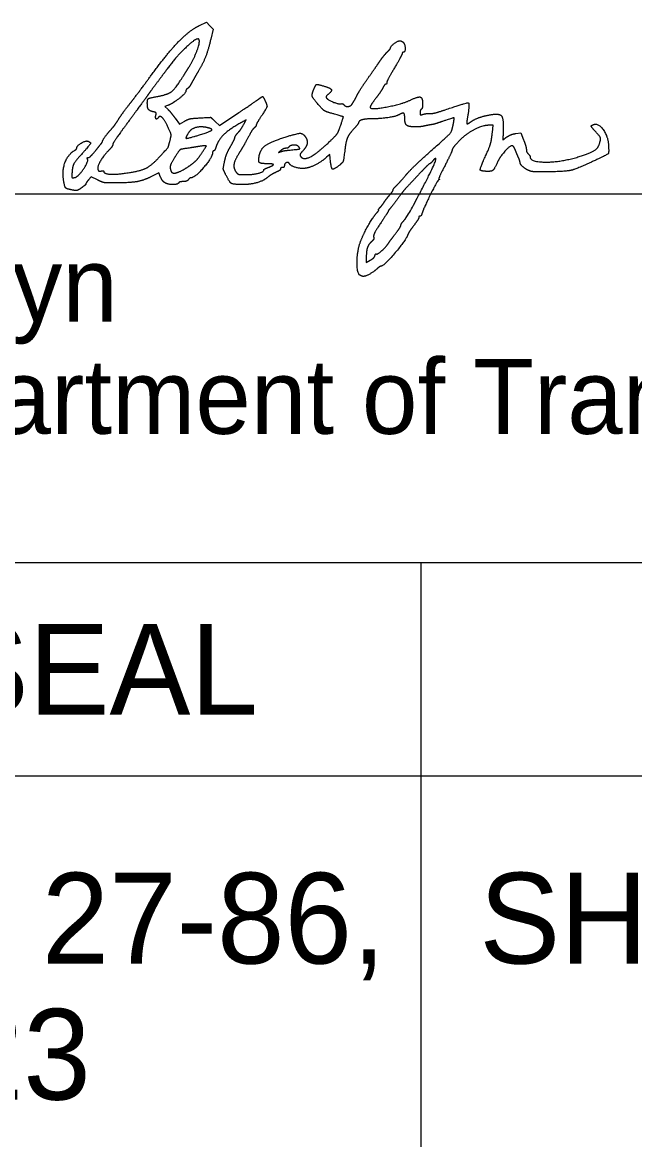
# Model space of a CAD drawing. Extents: x -21.9 to 47.3, y 14.1 to 48.7.
# Drawn here: x 25.653 to 26.801, y 33.152 to 35.245 of the extents above; entities that cross this region are included whole.
import ezdxf

# ---------------------------------------------------------------- set-up
doc = ezdxf.new("R2010")
doc.units = 0
for name, color, linetype in [('GM_X_City_Street', 7, 'Continuous'), ('SH_Data', 7, 'Continuous'), ('SH_Text', 7, 'Continuous')]:
    doc.layers.add(name, color=color, linetype=linetype)

msp = doc.modelspace()

# ---------------------------------------------------------------- linework, layer by layer
at = {"layer": 'GM_X_City_Street'}
for points in [[(25.9853, 35.2396), (25.9979, 35.2455), (26.0042, 35.2391), (26.0106, 35.2327), (26.0062, 35.214)], [(25.9253, 35.0896), (25.9203, 35.088), (25.9255, 35.0829)], [(26.0143, 35.0599), (26.0224, 35.0523), (26.0587, 35.0764)], [(25.9392, 35.0662), (25.9477, 35.0547), (25.9565, 35.0599)], [(26.0682, 35.0547), (26.0726, 35.0626), (26.0671, 35.0597)], [(26.534, 35.0388), (26.5355, 35.0526), (26.5277, 35.0526)], [(26.5779, 35.0371), (26.5876, 35.0387), (26.5926, 35.0251)], [(26.23, 34.991), (26.2293, 34.9978), (26.2234, 34.9927)], [(25.9123, 34.9554), (25.909, 34.9634), (25.8951, 34.9565)], [(25.7937, 34.9503), (25.7822, 34.9561), (25.7771, 34.9503)], [(26.2977, 34.8049), (26.2977, 34.7955), (26.3052, 34.7998)]]:
    msp.add_lwpolyline(points, dxfattribs=at)
for points in [[(25.8957, 35.1477), (25.9254, 35.1883), (25.9672, 35.2312), (25.9853, 35.2396)], [(25.9838, 35.2138), (25.9802, 35.2174), (25.9416, 35.1817), (25.9262, 35.1604)], [(25.9655, 35.1618), (25.9749, 35.1766), (25.9869, 35.2107), (25.9838, 35.2138)], [(26.0062, 35.214), (26.0012, 35.1929), (25.992, 35.1693), (25.9826, 35.1534)], [(26.3367, 35.1896), (26.3403, 35.1932), (26.3433, 35.1969), (26.3433, 35.1977)], [(26.3433, 35.1977), (26.3433, 35.2005), (26.3565, 35.2108), (26.3602, 35.2109)], [(26.3602, 35.2109), (26.3623, 35.2109), (26.3652, 35.2097), (26.3668, 35.2081)], [(26.3668, 35.2081), (26.3703, 35.2046), (26.3707, 35.1894), (26.3673, 35.1894)], [(26.3013, 35.1414), (26.3092, 35.1526), (26.319, 35.1665), (26.3229, 35.1724)], [(26.3229, 35.1724), (26.3269, 35.1782), (26.3331, 35.1859), (26.3367, 35.1896)], [(26.3649, 35.1868), (26.3649, 35.1855), (26.3584, 35.1734), (26.3505, 35.16)], [(26.3673, 35.1894), (26.366, 35.1894), (26.3649, 35.1882), (26.3649, 35.1868)], [(25.9262, 35.1604), (25.9226, 35.1555), (25.9132, 35.1428), (25.9053, 35.1323)], [(25.955, 35.1451), (25.9583, 35.1503), (25.963, 35.1578), (25.9655, 35.1618)], [(25.9826, 35.1534), (25.9791, 35.1474), (25.9739, 35.1382), (25.971, 35.133)], [(26.3505, 35.16), (26.3426, 35.1466), (26.3361, 35.1342), (26.3361, 35.1325)], [(25.8555, 35.0943), (25.8644, 35.1056), (25.8825, 35.1297), (25.8957, 35.1477)], [(25.9053, 35.1323), (25.8974, 35.1218), (25.8893, 35.1108), (25.8873, 35.1079)], [(25.9052, 35.1064), (25.9258, 35.1102), (25.9398, 35.1211), (25.955, 35.1451)], [(25.971, 35.133), (25.9682, 35.1277), (25.9644, 35.1225), (25.9626, 35.1214)], [(26.2799, 35.1078), (26.2837, 35.115), (26.2933, 35.1301), (26.3013, 35.1414)], [(26.3361, 35.1325), (26.3361, 35.1308), (26.3352, 35.1294), (26.3341, 35.1294)], [(25.9593, 35.116), (25.9593, 35.1123), (25.9335, 35.0922), (25.9253, 35.0896)], [(25.9626, 35.1214), (25.9608, 35.1204), (25.9593, 35.1179), (25.9593, 35.116)], [(26.209, 35.0902), (26.1975, 35.1032), (26.1953, 35.11), (26.1992, 35.1196)], [(26.1992, 35.1196), (26.203, 35.1287), (26.2061, 35.1297), (26.2188, 35.1259)], [(26.2188, 35.1259), (26.2308, 35.1224), (26.2337, 35.1162), (26.226, 35.1104)], [(26.226, 35.1104), (26.2233, 35.1083), (26.2218, 35.1054), (26.2228, 35.1041)], [(26.3288, 35.1228), (26.3271, 35.1191), (26.3209, 35.11), (26.3152, 35.1026)], [(26.3341, 35.1294), (26.333, 35.1294), (26.3306, 35.1264), (26.3288, 35.1228)], [(25.834, 35.0649), (25.837, 35.0697), (25.8467, 35.0829), (25.8555, 35.0943)], [(25.8873, 35.1079), (25.8853, 35.1049), (25.87, 35.084), (25.8532, 35.0613)], [(25.8873, 35.0943), (25.8873, 35.1012), (25.8914, 35.1039), (25.9052, 35.1064)], [(25.8983, 35.0779), (25.8911, 35.0797), (25.8873, 35.0854), (25.8873, 35.0943)], [(26.0587, 35.0764), (26.0786, 35.0897), (26.0962, 35.1016), (26.0978, 35.1029)], [(26.0978, 35.1029), (26.1023, 35.1067), (26.1047, 35.1058), (26.1077, 35.0992)], [(26.1077, 35.0992), (26.1121, 35.0896), (26.1111, 35.0855), (26.1009, 35.0696)], [(26.2325, 35.075), (26.2217, 35.0781), (26.2168, 35.0813), (26.209, 35.0902)], [(26.2228, 35.1041), (26.2254, 35.1003), (26.2453, 35.0921), (26.25, 35.0929)], [(26.25, 35.0929), (26.2522, 35.0933), (26.2548, 35.0924), (26.2556, 35.0911)], [(26.2556, 35.0911), (26.2578, 35.0876), (26.2678, 35.0879), (26.2706, 35.0916)], [(26.2706, 35.0916), (26.2719, 35.0932), (26.2761, 35.1005), (26.2799, 35.1078)], [(26.3152, 35.1026), (26.3096, 35.0951), (26.3049, 35.0878), (26.3049, 35.0865)], [(26.3049, 35.0865), (26.3049, 35.0812), (26.3645, 35.0921), (26.3825, 35.1007)], [(26.3825, 35.1007), (26.3955, 35.1069), (26.4033, 35.1037), (26.4033, 35.0924)], [(26.4033, 35.0924), (26.4033, 35.0878), (26.4022, 35.0834), (26.4009, 35.0826)], [(26.4456, 35.0816), (26.486, 35.0955), (26.4919, 35.0939), (26.4878, 35.07)], [(25.9034, 35.0716), (25.9043, 35.0752), (25.9031, 35.0767), (25.8983, 35.0779)], [(25.9077, 35.0669), (25.9052, 35.063), (25.902, 35.0665), (25.9034, 35.0716)], [(25.9265, 35.0483), (25.9203, 35.0619), (25.9106, 35.0716), (25.9077, 35.0669)], [(25.9255, 35.0829), (25.9283, 35.0801), (25.9345, 35.0726), (25.9392, 35.0662)], [(26.1009, 35.0696), (26.0956, 35.0615), (26.0913, 35.0539), (26.0913, 35.0528)], [(26.2493, 35.0513), (26.255, 35.0681), (26.2546, 35.0687), (26.2325, 35.075)], [(26.3583, 35.0719), (26.3527, 35.0689), (26.3225, 35.0646), (26.3075, 35.0646)], [(26.3697, 35.0672), (26.3697, 35.0745), (26.366, 35.0761), (26.3583, 35.0719)], [(26.4009, 35.0826), (26.3996, 35.0817), (26.3985, 35.0789), (26.3985, 35.0762)], [(26.3985, 35.0762), (26.3985, 35.0723), (26.3995, 35.0718), (26.4039, 35.0731)], [(26.4039, 35.0731), (26.4069, 35.0741), (26.4127, 35.0747), (26.4168, 35.0746)], [(26.4168, 35.0746), (26.421, 35.0744), (26.4339, 35.0776), (26.4456, 35.0816)], [(26.4878, 35.07), (26.4865, 35.0624), (26.4857, 35.0558), (26.4862, 35.0553)], [(26.4938, 35.0592), (26.501, 35.0642), (26.5192, 35.0705), (26.5329, 35.0727)], [(26.5329, 35.0727), (26.5476, 35.075), (26.5552, 35.0646), (26.5544, 35.0433)], [(25.8177, 35.043), (25.8243, 35.0503), (25.8285, 35.0561), (25.834, 35.0649)], [(25.8532, 35.0613), (25.8364, 35.0387), (25.8226, 35.0185), (25.8225, 35.0166)], [(25.9298, 35.0238), (25.9323, 35.0336), (25.932, 35.0358), (25.9265, 35.0483)], [(25.9565, 35.0599), (25.963, 35.0638), (25.9706, 35.0655), (25.9857, 35.0664)], [(25.9975, 35.0486), (25.9866, 35.0508), (25.9693, 35.0457), (25.9649, 35.0391)], [(25.9857, 35.0664), (26.006, 35.0675), (26.0062, 35.0675), (26.0143, 35.0599)], [(25.9869, 35.0351), (26.0061, 35.041), (26.0101, 35.0461), (25.9975, 35.0486)], [(26.0671, 35.0597), (26.0437, 35.0471), (26.021, 35.0265), (26.0168, 35.014)], [(26.0554, 35.0365), (26.0608, 35.0425), (26.0633, 35.0461), (26.0682, 35.0547)], [(26.0877, 35.0478), (26.0858, 35.0462), (26.0827, 35.042), (26.0809, 35.0385)], [(26.0913, 35.0528), (26.0913, 35.0516), (26.0897, 35.0494), (26.0877, 35.0478)], [(26.231, 35.024), (26.2414, 35.034), (26.2455, 35.0402), (26.2493, 35.0513)], [(26.2833, 35.0574), (26.2833, 35.0565), (26.2791, 35.0511), (26.2739, 35.0453)], [(26.3075, 35.0646), (26.296, 35.0646), (26.2833, 35.0608), (26.2833, 35.0574)], [(26.389, 35.0496), (26.3766, 35.0496), (26.3697, 35.0559), (26.3697, 35.0672)], [(26.4057, 35.051), (26.4024, 35.0502), (26.3949, 35.0496), (26.389, 35.0496)], [(26.4189, 35.0536), (26.4149, 35.0529), (26.409, 35.0518), (26.4057, 35.051)], [(26.4161, 35.002), (26.4516, 35.0336), (26.4585, 35.0418), (26.4609, 35.055)], [(26.4403, 35.0597), (26.4325, 35.057), (26.4229, 35.0542), (26.4189, 35.0536)], [(26.4609, 35.055), (26.463, 35.0665), (26.4613, 35.0669), (26.4403, 35.0597)], [(26.5277, 35.0526), (26.515, 35.0526), (26.4812, 35.0341), (26.4691, 35.0206)], [(26.4862, 35.0553), (26.4867, 35.0548), (26.4901, 35.0566), (26.4938, 35.0592)], [(26.7245, 35.0439), (26.7192, 35.0496), (26.719, 35.0523), (26.7236, 35.054)], [(26.7236, 35.054), (26.7322, 35.0573), (26.7506, 35.0324), (26.7516, 35.0161)], [(25.8033, 35.0225), (25.8033, 35.0242), (25.8124, 35.0372), (25.8177, 35.043)], [(25.9649, 35.0391), (25.9579, 35.0284), (25.9625, 35.0276), (25.9869, 35.0351)], [(26.0429, 35.0124), (26.0473, 35.0201), (26.0512, 35.0278), (26.0514, 35.0295)], [(26.0514, 35.0295), (26.0517, 35.0312), (26.0535, 35.0344), (26.0554, 35.0365)], [(26.0809, 35.0385), (26.0727, 35.0231), (26.0649, 35.0093), (26.0588, 34.9996)], [(26.0971, 34.9957), (26.0992, 35.007), (26.1154, 35.0204), (26.1347, 35.0268)], [(26.1347, 35.0268), (26.1665, 35.0374), (26.1799, 35.0378), (26.185, 35.0284)], [(26.185, 35.0284), (26.1882, 35.0223), (26.1848, 35.0109), (26.1774, 35.003)], [(26.2739, 35.0453), (26.2655, 35.0359), (26.2597, 35.0233), (26.2581, 35.0106)], [(26.5194, 34.9909), (26.5284, 35.0108), (26.5324, 35.024), (26.534, 35.0388)], [(26.5544, 35.0433), (26.5537, 35.0249), (26.5536, 35.0252), (26.5613, 35.0307)], [(26.5613, 35.0307), (26.5651, 35.0334), (26.5726, 35.0363), (26.5779, 35.0371)], [(26.7336, 35.0148), (26.7376, 35.0266), (26.736, 35.0315), (26.7245, 35.0439)], [(25.7304, 34.9489), (25.7275, 34.9674), (25.7382, 34.9975), (25.7506, 35.0052)], [(25.7506, 35.0052), (25.7532, 35.0068), (25.7553, 35.0092), (25.7553, 35.0105)], [(25.7553, 35.0105), (25.7554, 35.0143), (25.7721, 35.0243), (25.7759, 35.0228)], [(25.7759, 35.0228), (25.7819, 35.0205), (25.7796, 35.0156), (25.7653, 34.9997)], [(25.7888, 35.0034), (25.7941, 35.01), (25.7996, 35.0167), (25.8009, 35.0182)], [(25.8151, 35.0058), (25.8053, 34.9962), (25.7929, 34.9741), (25.7947, 34.9694)], [(25.8009, 35.0182), (25.8022, 35.0198), (25.8033, 35.0218), (25.8033, 35.0225)], [(25.8225, 35.0166), (25.8224, 35.0146), (25.8191, 35.0097), (25.8151, 35.0058)], [(25.9101, 34.9933), (25.9262, 35.0108), (25.9265, 35.0113), (25.9298, 35.0238)], [(25.9677, 35.0103), (25.9499, 35.0077), (25.9479, 35.0066), (25.9406, 34.9954)], [(25.9851, 35.013), (25.9795, 35.0121), (25.9717, 35.0109), (25.9677, 35.0103)], [(25.9901, 35.0013), (25.9979, 35.0127), (25.997, 35.0148), (25.9851, 35.013)], [(26.0168, 35.014), (26.0151, 35.0088), (26.0128, 35.0046), (26.0117, 35.0046)], [(26.032, 34.9846), (26.0336, 34.9923), (26.0385, 35.0048), (26.0429, 35.0124)], [(26.138, 35.0056), (26.1334, 35.0018), (26.1334, 35.0018), (26.1381, 35.0034)], [(26.1468, 35.0094), (26.1445, 35.0094), (26.1405, 35.0076), (26.138, 35.0056)], [(26.1381, 35.0034), (26.1407, 35.0044), (26.1483, 35.0056), (26.1549, 35.0062)], [(26.1523, 35.0115), (26.1516, 35.0103), (26.1491, 35.0094), (26.1468, 35.0094)], [(26.1708, 35.0126), (26.168, 35.0159), (26.1546, 35.0151), (26.1523, 35.0115)], [(26.1549, 35.0062), (26.1716, 35.0077), (26.174, 35.0087), (26.1708, 35.0126)], [(26.174, 34.9951), (26.1793, 34.9865), (26.2061, 35), (26.231, 35.024)], [(26.2581, 35.0106), (26.2553, 34.9881), (26.2536, 34.9826), (26.2479, 34.9781)], [(26.4585, 35.006), (26.4585, 35.0044), (26.4525, 34.9916), (26.4453, 34.9774)], [(26.4691, 35.0206), (26.4632, 35.0141), (26.4585, 35.0075), (26.4585, 35.006)], [(26.5709, 35.0142), (26.5666, 35.0142), (26.5483, 34.9936), (26.5436, 34.9835)], [(26.5765, 35.0076), (26.575, 35.0112), (26.5725, 35.0142), (26.5709, 35.0142)], [(26.5824, 34.9934), (26.5806, 34.9975), (26.578, 35.0039), (26.5765, 35.0076)], [(26.5926, 35.0251), (26.5954, 35.0177), (26.5977, 35.0095), (26.5977, 35.007)], [(26.5977, 35.007), (26.5977, 35.0045), (26.5993, 35.0009), (26.6013, 34.9989)], [(26.6847, 34.9905), (26.7084, 34.9968), (26.7314, 35.0082), (26.7336, 35.0148)], [(26.7516, 35.0161), (26.7526, 35.0008), (26.7499, 34.9977), (26.7265, 34.9867)], [(25.7653, 34.9997), (25.7516, 34.9846), (25.7466, 34.9744), (25.746, 34.9606)], [(25.7509, 34.9546), (25.7572, 34.9555), (25.7773, 34.984), (25.7753, 34.9892)], [(25.7753, 34.9892), (25.7745, 34.9911), (25.7751, 34.9924), (25.7765, 34.992)], [(25.7765, 34.992), (25.7779, 34.9917), (25.7834, 34.9968), (25.7888, 35.0034)], [(25.8536, 34.9639), (25.8763, 34.9676), (25.8959, 34.9778), (25.9101, 34.9933)], [(25.9406, 34.9954), (25.9324, 34.9827), (25.9292, 34.9729), (25.9315, 34.9671)], [(25.9602, 34.9726), (25.9714, 34.9796), (25.9824, 34.9901), (25.9901, 35.0013)], [(26.0097, 35.0016), (26.0095, 34.993), (25.9764, 34.9542), (25.9693, 34.9542)], [(26.0117, 35.0046), (26.0106, 35.0046), (26.0097, 35.0032), (26.0097, 35.0016)], [(26.034, 34.9606), (26.0296, 34.9697), (26.0294, 34.9719), (26.032, 34.9846)], [(26.0588, 34.9996), (26.0508, 34.987), (26.0486, 34.9718), (26.0537, 34.965)], [(26.1106, 34.9806), (26.0991, 34.9806), (26.0951, 34.9851), (26.0971, 34.9957)], [(26.1774, 35.003), (26.1746, 35.0001), (26.1731, 34.9965), (26.174, 34.9951)], [(26.2234, 34.9927), (26.214, 34.9845), (26.194, 34.9739), (26.1849, 34.9722)], [(26.2479, 34.9781), (26.2362, 34.9689), (26.2318, 34.972), (26.23, 34.991)], [(26.3694, 34.8755), (26.3771, 34.8842), (26.4303, 34.988), (26.4282, 34.99)], [(26.372, 34.9593), (26.3792, 34.9677), (26.399, 34.9869), (26.4161, 35.002)], [(26.4225, 34.986), (26.4201, 34.983), (26.4175, 34.9806), (26.4167, 34.9806)], [(26.4282, 34.99), (26.4275, 34.9908), (26.4249, 34.9889), (26.4225, 34.986)], [(26.5267, 34.9662), (26.5122, 34.9662), (26.5106, 34.9716), (26.5194, 34.9909)], [(26.5858, 34.9838), (26.5857, 34.9849), (26.5842, 34.9892), (26.5824, 34.9934)], [(26.6013, 34.9989), (26.6033, 34.9969), (26.6049, 34.9942), (26.6049, 34.9929)], [(26.6049, 34.9929), (26.6049, 34.9844), (26.6555, 34.9829), (26.6847, 34.9905)], [(26.7265, 34.9867), (26.6917, 34.9704), (26.6707, 34.9656), (26.6313, 34.9652)], [(25.7947, 34.9694), (25.7956, 34.967), (25.7979, 34.9661), (25.8009, 34.9669)], [(25.8009, 34.9669), (25.8035, 34.9675), (25.8057, 34.9672), (25.8057, 34.9661)], [(25.8057, 34.9661), (25.8057, 34.9615), (25.8313, 34.9603), (25.8536, 34.9639)], [(25.9315, 34.9671), (25.9335, 34.9618), (25.9471, 34.9645), (25.9602, 34.9726)], [(26.0537, 34.965), (26.0566, 34.9612), (26.0601, 34.9602), (26.0713, 34.9602)], [(26.0713, 34.9602), (26.0853, 34.9601), (26.1057, 34.9653), (26.1057, 34.9688)], [(26.1057, 34.9688), (26.1057, 34.9698), (26.1094, 34.972), (26.114, 34.9736)], [(26.114, 34.9736), (26.1243, 34.9774), (26.1227, 34.9806), (26.1106, 34.9806)], [(26.1315, 34.966), (26.1242, 34.9627), (26.1165, 34.9582), (26.1123, 34.9546)], [(26.1369, 34.9709), (26.1369, 34.9695), (26.1345, 34.9673), (26.1315, 34.966)], [(26.1405, 34.9734), (26.1385, 34.9734), (26.1369, 34.9722), (26.1369, 34.9709)], [(26.1441, 34.9767), (26.1441, 34.9749), (26.1425, 34.9734), (26.1405, 34.9734)], [(26.1536, 34.9807), (26.1516, 34.984), (26.1441, 34.9808), (26.1441, 34.9767)], [(26.1849, 34.9722), (26.1763, 34.9707), (26.1565, 34.976), (26.1536, 34.9807)], [(26.4079, 34.9728), (26.4038, 34.9685), (26.3933, 34.9574), (26.3845, 34.9481)], [(26.4167, 34.9806), (26.416, 34.9806), (26.412, 34.977), (26.4079, 34.9728)], [(26.4453, 34.9774), (26.438, 34.9633), (26.4329, 34.9517), (26.4339, 34.9517)], [(26.5436, 34.9835), (26.5379, 34.9711), (26.5331, 34.9662), (26.5267, 34.9662)], [(26.6014, 34.9682), (26.5944, 34.9715), (26.5859, 34.9799), (26.5858, 34.9838)], [(26.6313, 34.9652), (26.6164, 34.965), (26.6061, 34.966), (26.6014, 34.9682)], [(25.747, 34.9312), (25.7361, 34.9332), (25.7323, 34.9373), (25.7304, 34.9489)], [(25.746, 34.9606), (25.7458, 34.955), (25.7466, 34.954), (25.7509, 34.9546)], [(25.7721, 34.9427), (25.7721, 34.9418), (25.7683, 34.9384), (25.7637, 34.9353)], [(25.7771, 34.9503), (25.7744, 34.9471), (25.7721, 34.9437), (25.7721, 34.9427)], [(25.8245, 34.9446), (25.8089, 34.9446), (25.803, 34.9457), (25.7937, 34.9503)], [(25.8951, 34.9565), (25.8796, 34.9488), (25.8544, 34.9446), (25.8245, 34.9446)], [(25.9205, 34.9447), (25.9179, 34.9462), (25.9142, 34.951), (25.9123, 34.9554)], [(25.9461, 34.9446), (25.9441, 34.9414), (25.9266, 34.9415), (25.9205, 34.9447)], [(25.9543, 34.947), (25.9506, 34.947), (25.9469, 34.9459), (25.9461, 34.9446)], [(25.9641, 34.9506), (25.9625, 34.9486), (25.9581, 34.947), (25.9543, 34.947)], [(25.9693, 34.9542), (25.9681, 34.9542), (25.9657, 34.9525), (25.9641, 34.9506)], [(26.0658, 34.9414), (26.0483, 34.9415), (26.0413, 34.9458), (26.034, 34.9606)], [(26.1123, 34.9546), (26.1046, 34.9483), (26.0803, 34.9414), (26.0658, 34.9414)], [(26.3535, 34.9389), (26.3565, 34.9417), (26.3648, 34.9509), (26.372, 34.9593)], [(26.3845, 34.9481), (26.3757, 34.9388), (26.3658, 34.9276), (26.3625, 34.9231)], [(26.4331, 34.9499), (26.4304, 34.9481), (26.4052, 34.8971), (26.4022, 34.8876)], [(26.4339, 34.9517), (26.4349, 34.9517), (26.4345, 34.9509), (26.4331, 34.9499)], [(25.7637, 34.9353), (25.7572, 34.9308), (25.7536, 34.9299), (25.747, 34.9312)], [(26.3313, 34.9085), (26.3333, 34.9116), (26.3379, 34.9176), (26.3415, 34.9218)], [(26.3625, 34.9231), (26.3544, 34.9122), (26.3439, 34.8984), (26.3409, 34.8949)], [(26.3415, 34.9218), (26.3451, 34.9261), (26.3481, 34.9305), (26.3481, 34.9317)], [(26.3481, 34.9317), (26.3482, 34.9328), (26.3506, 34.9361), (26.3535, 34.9389)], [(26.3235, 34.8986), (26.3258, 34.901), (26.3293, 34.9055), (26.3313, 34.9085)], [(26.2875, 34.8362), (26.2934, 34.851), (26.3105, 34.8809), (26.3176, 34.8888)], [(26.3176, 34.8888), (26.3203, 34.8917), (26.3218, 34.8942), (26.3209, 34.8942)], [(26.3209, 34.8942), (26.32, 34.8942), (26.3212, 34.8961), (26.3235, 34.8986)], [(26.3385, 34.891), (26.3385, 34.8904), (26.3322, 34.8805), (26.3244, 34.8688)], [(26.3409, 34.8949), (26.3396, 34.8933), (26.3385, 34.8915), (26.3385, 34.891)], [(26.3961, 34.8796), (26.3961, 34.8783), (26.3918, 34.8715), (26.3866, 34.8646)], [(26.3983, 34.8822), (26.3971, 34.8822), (26.3961, 34.881), (26.3961, 34.8796)], [(26.4022, 34.8876), (26.4013, 34.8846), (26.3996, 34.8822), (26.3983, 34.8822)], [(26.3244, 34.8688), (26.3158, 34.8558), (26.3108, 34.846), (26.3115, 34.8433)], [(26.3523, 34.8493), (26.3579, 34.8567), (26.3625, 34.8638), (26.3625, 34.8652)], [(26.3625, 34.8652), (26.3625, 34.8665), (26.3656, 34.8711), (26.3694, 34.8755)], [(26.3866, 34.8646), (26.3814, 34.8577), (26.3763, 34.8497), (26.3752, 34.8469)], [(26.3115, 34.8433), (26.3122, 34.8408), (26.3106, 34.8372), (26.3078, 34.8348)], [(26.3752, 34.8469), (26.3716, 34.837), (26.3304, 34.7886), (26.3257, 34.7886)], [(26.3397, 34.8321), (26.341, 34.8342), (26.3467, 34.842), (26.3523, 34.8493)], [(26.2857, 34.7717), (26.2798, 34.7755), (26.281, 34.8198), (26.2875, 34.8362)], [(26.3078, 34.8348), (26.3019, 34.8295), (26.2977, 34.8172), (26.2977, 34.8049)], [(26.3169, 34.8113), (26.3188, 34.8102), (26.3355, 34.8253), (26.3397, 34.8321)], [(26.3052, 34.7998), (26.3094, 34.8022), (26.3133, 34.806), (26.3139, 34.8083)], [(26.3139, 34.8083), (26.3145, 34.8106), (26.3159, 34.812), (26.3169, 34.8113)], [(26.3183, 34.784), (26.3121, 34.7783), (26.2961, 34.7693), (26.2922, 34.7694)], [(26.3257, 34.7886), (26.3243, 34.7886), (26.321, 34.7865), (26.3183, 34.784)], [(26.2922, 34.7694), (26.2906, 34.7694), (26.2877, 34.7705), (26.2857, 34.7717)]]:
    msp.add_open_spline(points, degree=2, dxfattribs=at)
at = {"layer": 'SH_Data'}
for p, q in [((24.5, 34.9244), (28, 34.9244)), ((23.6, 34.2334), (26.4, 34.2334)), ((26.4, 34.2334), (26.4, 30.7334)), ((26.4, 34.2334), (29.2, 34.2334)), ((23.6, 33.8334), (26.4, 33.8334)), ((26.4, 33.8334), (29.2, 33.8334))]:
    msp.add_line(p, q, dxfattribs=at)

# ---------------------------------------------------------------- texts
msp.add_text("ENGINEER'S SEAL", height=0.17, dxfattribs=at).set_placement((24.0676, 33.9484))
at = {"layer": 'SH_Text'}
for s, height, p in [('Pamela Boratyn', 0.14, (24.5, 34.6844)), ('Director, Department of Transportation', 0.14, (24.5, 34.4744)), ('SHEETS: 1-21, 25, 27-86,', 0.17, (23.6931, 33.4819)), ('SHEETS: 22-24, 103-120', 0.17, (26.5095, 33.4819)), ('97-102, 121-123', 0.17, (24.1129, 33.2269))]:
    msp.add_text(s, height=height, dxfattribs=at).set_placement(p)

doc.saveas('drawing.dxf')
